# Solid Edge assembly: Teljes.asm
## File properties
Author: morva
Template: Iso Metric Assembly.asm
Last saved by: morva
Revision: 30
Application: Solid Edge
Username: morva
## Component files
NewDeckAssembly.asm
k.asm
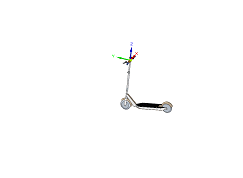
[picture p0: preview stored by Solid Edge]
